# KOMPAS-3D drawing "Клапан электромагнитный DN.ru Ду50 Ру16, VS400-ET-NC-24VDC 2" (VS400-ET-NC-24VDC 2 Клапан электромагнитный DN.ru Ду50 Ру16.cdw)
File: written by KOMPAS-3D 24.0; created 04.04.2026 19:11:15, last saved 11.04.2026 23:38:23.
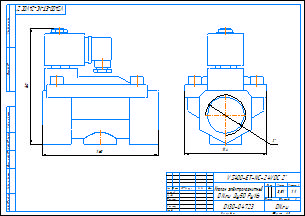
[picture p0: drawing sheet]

Document properties: c3d_UniqueCompID: ef56311e-7521-43dc-8291-0e6108b3d81d; Обозначение: VS400-ET-NC-220VAC 2; Наименование: Клапан электромагнитный DN.ru Ду50 Ру16; Автор: artio; Класс точности: c; Знак неуказанной шероховатости: Шероховатость не задана; Рассекать на разрезах: Да; c3d_UniqueCompID: ef56311e-7521-43dc-8291-0e6108b3d81d; Обозначение: VS400-ET-NC-220VAC 1; Наименование: Клапан электромагнитный DN.ru Ду25 Ру16; Автор: artio; Класс точности: c; Знак неуказанной шероховатости: Шероховатость не задана; Рассекать на разрезах: Да; c3d_UniqueCompID: ef56311e-7521-43dc-8291-0e6108b3d81d; Обозначение: VS400-ET-NC-220VAC 1-2; Наименование: Клапан электромагнитный DN.ru Ду15 Ру16; Автор: artio; Класс точности: c; Знак неуказанной шероховатости: Шероховатость не задана; Рассекать на разрезах: Да; c3d_UniqueCompID: ef56311e-7521-43dc-8291-0e6108b3d81d; Обозначение: VS400-ET-NC-220VAC 3-4; Наименование: Клапан электромагнитный DN.ru Ду20 Ру16; Автор: artio; Класс точности: c; Знак неуказанной шероховатости: Шероховатость не задана; Рассекать на разрезах: Да; c3d_UniqueCompID: ef56311e-7521-43dc-8291-0e6108b3d81d; Обозначение: VS400-ET-NC-220VAC 1 1-4; Наименование: Клапан электромагнитный DN.ru Ду32 Ру16; Автор: artio; Класс точности: c; Знак неуказанной шероховатости: Шероховатость не задана; Рассекать на разрезах: Да; c3d_UniqueCompID: ef56311e-7521-43dc-8291-0e6108b3d81d; Обозначение: VS400-ET-NC-220VAC 3-8; Наименование: Клапан электромагнитный DN.ru Ду10 Ру16; Автор: artio; Класс точности: c; Знак неуказанной шероховатости: Шероховатость не задана; Рассекать на разрезах: Да; c3d_UniqueCompID: ef56311e-7521-43dc-8291-0e6108b3d81d; Обозначение: VS400-ET-NC-220VAC 1 1-2; Наименование: Клапан электромагнитный DN.ru Ду40 Ру16; Автор: artio; Класс точности: c; Знак неуказанной шероховатости: Шероховатость не задана; Рассекать на разрезах: Да; Автор: artio; Форматы листов документа: A3; Полное имя файла: VS400-ET-NC-24VDC 2 Клапан электромагнитный DN.ru Ду50 Ру16.m3d; Масса: 3.509; Наименование: Клапан электромагнитный DN.ru Ду50 Ру16; Количество листов документа: 1; Примечание: D130-04724

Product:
- Body: Тело 1  | qty 1
    Масса: 7.119215
- Part/product: Клапан электромагнитный DN.ru Ду50 Ру16  | designation VS400-ET-NC-24VDC 2
    Масса: 3.509
    Раздел спецификации: Прочие изделия
    Примечание: D130-04724
    additional columns: ef56311e-7521-43dc-8291-0e6108b3d81d; VS400-ET-NC-220VAC 2; artio; c; Шероховатость не задана; Да

Views: Вид 1, Спереди
Referenced files in C:\Users\artio\OneDrive\Рабочий стол\Клапан электромагнитный DN.ru\VS400-ET-NC\VS400-ET-NC-24VDC\: VS400-ET-NC-24VDC 3-8 Клапан электромагнитный DN.ru Ду10 Ру16.m3d, VS400-ET-NC-24VDC 2 Клапан электромагнитный DN.ru Ду50 Ру16.m3d
Referenced files in C:\Users\artio\OneDrive\Рабочий стол\Клапан электромагнитный DN.ru\VS400-ET-NC\: VS400-ET-NC-24VDC 3-8 Клапан электромагнитный DN.ru Ду10 Ру16.cdw
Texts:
  VS400-ET-NC-24VDC 2
  Клапан электромагнитный
  DN.ru Ду50 Ру16
  VS400-ET-NC-24VDC 2"
  VS400-ET-NC-24VDC 2"-
  Клапан электромагнитный DN.ru Ду50 Ру16
  VS400-ET-NC-24VDC 2 Клапан электромагнитный DN.ru Ду50 Ру16
Dimensions and other numbers on the sheet: 0; 3; 2; 4; 114; 1:1; 1; 3,51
